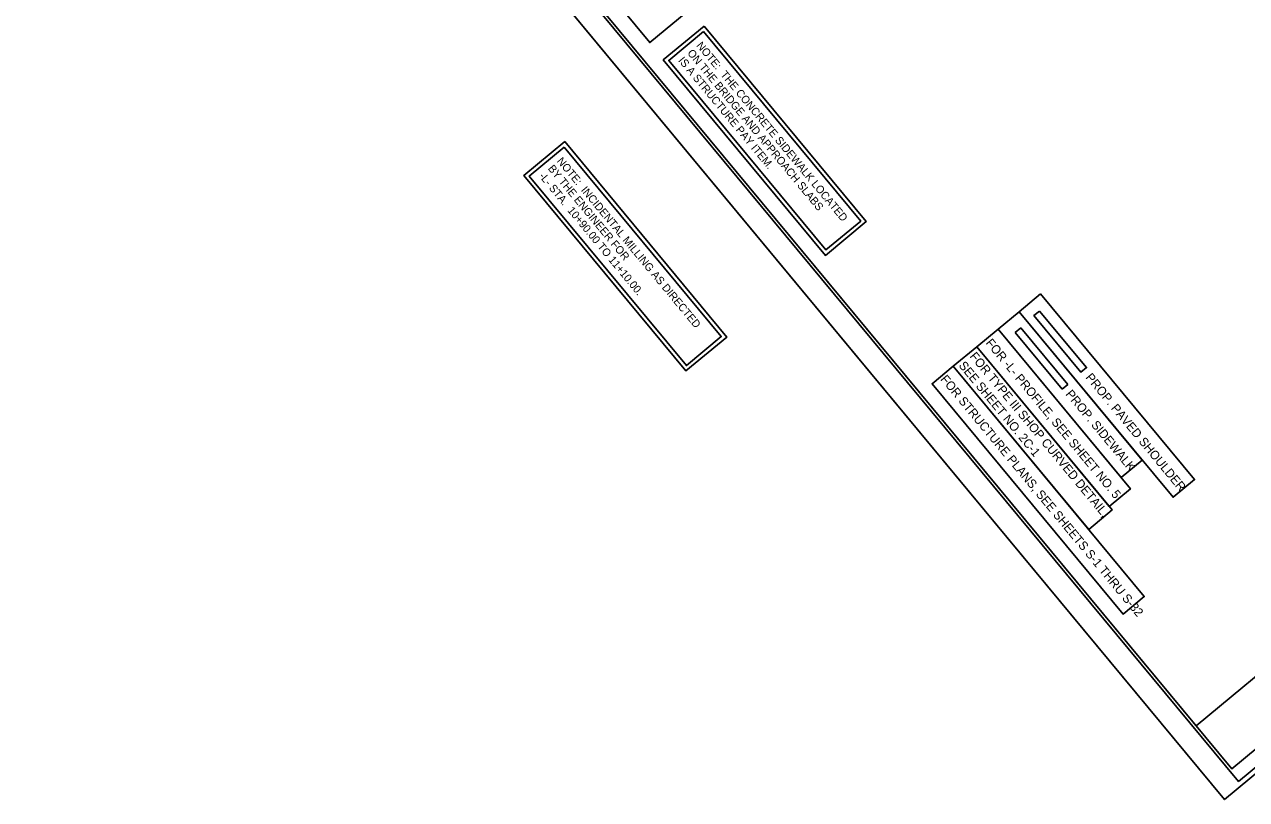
# Model space of a CAD drawing. Extents: x 2057815 to 2059783, y 687683 to 689713.
# Drawn here: x 2057815 to 2058909, y 687683 to 688377 of the extents above; entities that cross this region are included whole.
import ezdxf

# ---------------------------------------------------------------- set-up
doc = ezdxf.new("R2010")
doc.units = 0
for name, color, linetype in [('Prop Conc 4in Sidewalk', 7, 'Continuous'), ('Prop Dimension Text', 7, 'Continuous'), ('Prop Horizontal Alignment Station Label', 7, 'Continuous'), ('Prop Paved Shoulder', 7, 'Continuous'), ('Prop Shade Light', 7, 'Continuous'), ('Sheet Clip Boundary CELL', 7, 'Continuous'), ('Sheet Cutting Line CELL', 7, 'Continuous'), ('Sheet Layout Plan Border', 7, 'Continuous'), ('Sheet Plan CELL', 7, 'Continuous'), ('Sheet Plan Layout CELL', 7, 'Continuous'), ('Sheet Plot Border Inside CELL', 7, 'Continuous'), ('Sheet Plot Border Outside CELL', 7, 'Continuous')]:
    doc.layers.add(name, color=color, linetype=linetype)

msp = doc.modelspace()

# ---------------------------------------------------------------- linework, layer by layer
at = {"layer": 'Prop Conc 4in Sidewalk'}
for p, q in [((2058702.2, 688101.4), (2058707.2, 688105.6)), ((2058744.3, 688050.7), (2058702.2, 688101.4)), ((2058707.2, 688105.6), (2058749.3, 688054.8)), ((2058749.3, 688054.8), (2058744.3, 688050.7))]:
    msp.add_line(p, q, dxfattribs=at)
at = {"layer": 'Prop Dimension Text'}
for points in [[(2058256.1, 688853), (2058546.3, 688503.1), (2058374.9, 688361.1), (2058084.8, 688711)], [(2058423.7, 688375.9), (2058568.8, 688200.9), (2058532.2, 688170.5), (2058387.1, 688345.6)], [(2058423.2, 688371), (2058563.9, 688201.3), (2058532.7, 688175.4), (2058392, 688345.1)], [(2058298.8, 688272.4), (2058444, 688097.3), (2058407.4, 688067), (2058262.2, 688242)], [(2058298.4, 688267.4), (2058439, 688097.8), (2058407.8, 688071.9), (2058267.1, 688241.5)]]:
    msp.add_lwpolyline(points, close=True, dxfattribs=at)
at = {"layer": 'Prop Horizontal Alignment Station Label'}
for points in [[(2058725, 688136), (2058862.8, 687969.8), (2058843.6, 687953.9), (2058705.8, 688120.1)], [(2058705.8, 688120.1), (2058816, 687987.2), (2058797, 687971.5), (2058686.8, 688104.4)], [(2058686.8, 688104.4), (2058805.3, 687961.4), (2058786.4, 687945.7), (2058667.8, 688088.6)], [(2058667.8, 688088.6), (2058789, 687942.5), (2058768, 687925.1), (2058646.8, 688071.2)], [(2058646.8, 688071.2), (2058817.8, 687865), (2058798.8, 687849.3), (2058627.8, 688055.5)]]:
    msp.add_lwpolyline(points, close=True, dxfattribs=at)
at = {"layer": 'Prop Paved Shoulder'}
msp.add_lwpolyline([(2058724, 688120.7), (2058766.1, 688070), (2058761.1, 688065.8), (2058719, 688116.6)], close=True, dxfattribs=at)
at = {"layer": 'Prop Shade Light'}
for p, q in [((2058719, 688116.6), (2058724, 688120.7)), ((2058724, 688120.7), (2058766.1, 688070)), ((2058761.1, 688065.8), (2058719, 688116.6)), ((2058766.1, 688070), (2058761.1, 688065.8))]:
    msp.add_line(p, q, dxfattribs=at)
at = {"layer": 'Sheet Clip Boundary CELL'}
msp.add_lwpolyline([(2057970.6, 688826.8), (2058864.2, 687749.1), (2059509.7, 688284.3), (2059388.9, 688430), (2059551.7, 688565), (2058778.8, 689497)], close=True, dxfattribs=at)
at = {"layer": 'Sheet Cutting Line CELL'}
msp.add_line((2057815.1, 688979), (2058889.7, 687683.1), dxfattribs=at)
at = {"layer": 'Sheet Layout Plan Border'}
msp.add_lwpolyline([(2057970.6, 688826.8), (2058864.2, 687749.1), (2059509.7, 688284.3), (2059388.9, 688430), (2059551.7, 688565), (2058778.8, 689497)], close=True, dxfattribs=at)
at = {"layer": 'Sheet Plan CELL'}
for points in [[(2059704.4, 688380.8), (2058746.9, 689535.5), (2057938.7, 688865.2), (2058896.2, 687710.6)], [(2057938.7, 688865.2), (2058746.9, 689535.5), (2059576.7, 688534.8), (2059461.2, 688439), (2059588.9, 688285), (2058896.2, 687710.6)]]:
    msp.add_lwpolyline(points, close=True, dxfattribs=at)
at = {"layer": 'Sheet Plan Layout CELL'}
msp.add_lwpolyline([(2058746.9, 689535.5), (2057938.7, 688865.2), (2058896.2, 687710.6), (2059541.6, 688245.8), (2059388.9, 688430), (2059551.7, 688565)], close=True, dxfattribs=at)
at = {"layer": 'Sheet Plot Border Inside CELL'}
msp.add_lwpolyline([(2057838.8, 688981.8), (2058902.2, 687699.4), (2059714.3, 688372.8), (2058650.9, 689655.2)], close=True, dxfattribs=at)
at = {"layer": 'Sheet Plot Border Outside CELL'}
msp.add_lwpolyline([(2057815.1, 688979), (2058889.7, 687683.1), (2059732.6, 688382.1), (2058658, 689678)], close=True, dxfattribs=at)

# ---------------------------------------------------------------- texts
at = {"layer": 'Prop Dimension Text'}
for s, height, p in [('NOTE:  THE CONCRETE SIDEWALK LOCATED', 7, (2058416.3, 688358.3)), ('ON THE BRIDGE AND APPROACH SLABS', 7, (2058408.2, 688351.6)), ('IS A STRUCTURE PAY ITEM.', 7, (2058400.1, 688344.9)), ('BY THE ENGINEER FOR', 7, (2058283.4, 688248.1)), ('NOTE:  INCIDENTAL MILLING AS DIRECTED', 7, (2058291.4, 688254.8)), ('-L- STA.  10+90.00 TO 11+10.00.', 7, (2058275.3, 688241.4)), ('FOR -L- PROFILE, SEE SHEET NO. 5', 7.897, (2058675.3, 688091.9)), ('SEE SHEET NO. 2C-1', 7.897, (2058651.1, 688071.7)), ('FOR TYPE III SHOP CURVED DETAIL,', 7.897, (2058661, 688079.9)), ('PROP. PAVED SHOULDER', 7.897, (2058764.7, 688061)), ('FOR STRUCTURE PLANS, SEE SHEETS S-1 THRU S-32', 7.897, (2058634.8, 688059.4)), ('PROP. SIDEWALK', 7.897, (2058746.9, 688046.1))]:
    msp.add_text(s, height=height, rotation=309.6672, dxfattribs=at).set_placement(p)

doc.saveas('drawing.dxf')
